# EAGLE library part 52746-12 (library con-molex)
FPC Connector ZIF for SMT 0.5mm Source: http://www.farnell.com/datasheets/73044.pdf [DWG. NO. (Sheet 1 OF 2) SD-52746-**17]
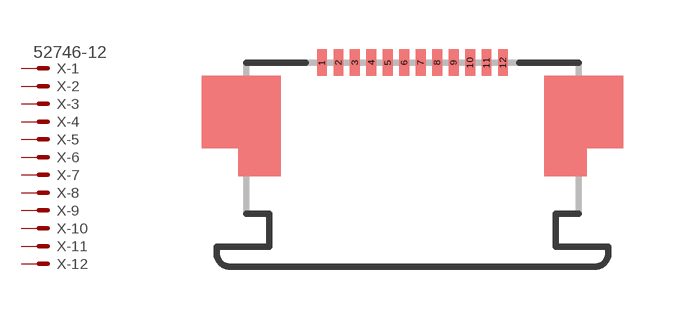
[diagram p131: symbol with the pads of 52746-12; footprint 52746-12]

Designator prefix X; gates -1=MV -2=M -3=M -4=M -5=M -6=M -7=M -8=M -9=M -10=M -11=M -12=M

## 52746-12 (OC_FARNELL: unknown; OC_NEWARK: unknown)  [52746-12]
1  -1:S  pas
2  -2:S  pas
3  -3:S  pas
4  -4:S  pas
5  -5:S  pas
6  -6:S  pas
7  -7:S  pas
8  -8:S  pas
9  -9:S  pas
10  -10:S  pas
11  -11:S  pas
12  -12:S  pas

## Footprint 52746-12 (pad centres in mm)
FPC Connector ZIF for SMT 0.5mm Source: http://www.farnell.com/datasheets/73044.pdf [DWG. NO. (Sheet 1 OF 2) SD-52746-**17]
smd 0.3 x 0.8: 1 -2.75,0.6; 2 -2.25,0.6; 3 -1.75,0.6; 4 -1.25,0.6; 5 -0.75,0.6; 6 -0.25,0.6; 7 0.25,0.6; 8 0.75,0.6; 9 1.25,0.6; 10 1.75,0.6; 11 2.25,0.6; 12 2.75,0.6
